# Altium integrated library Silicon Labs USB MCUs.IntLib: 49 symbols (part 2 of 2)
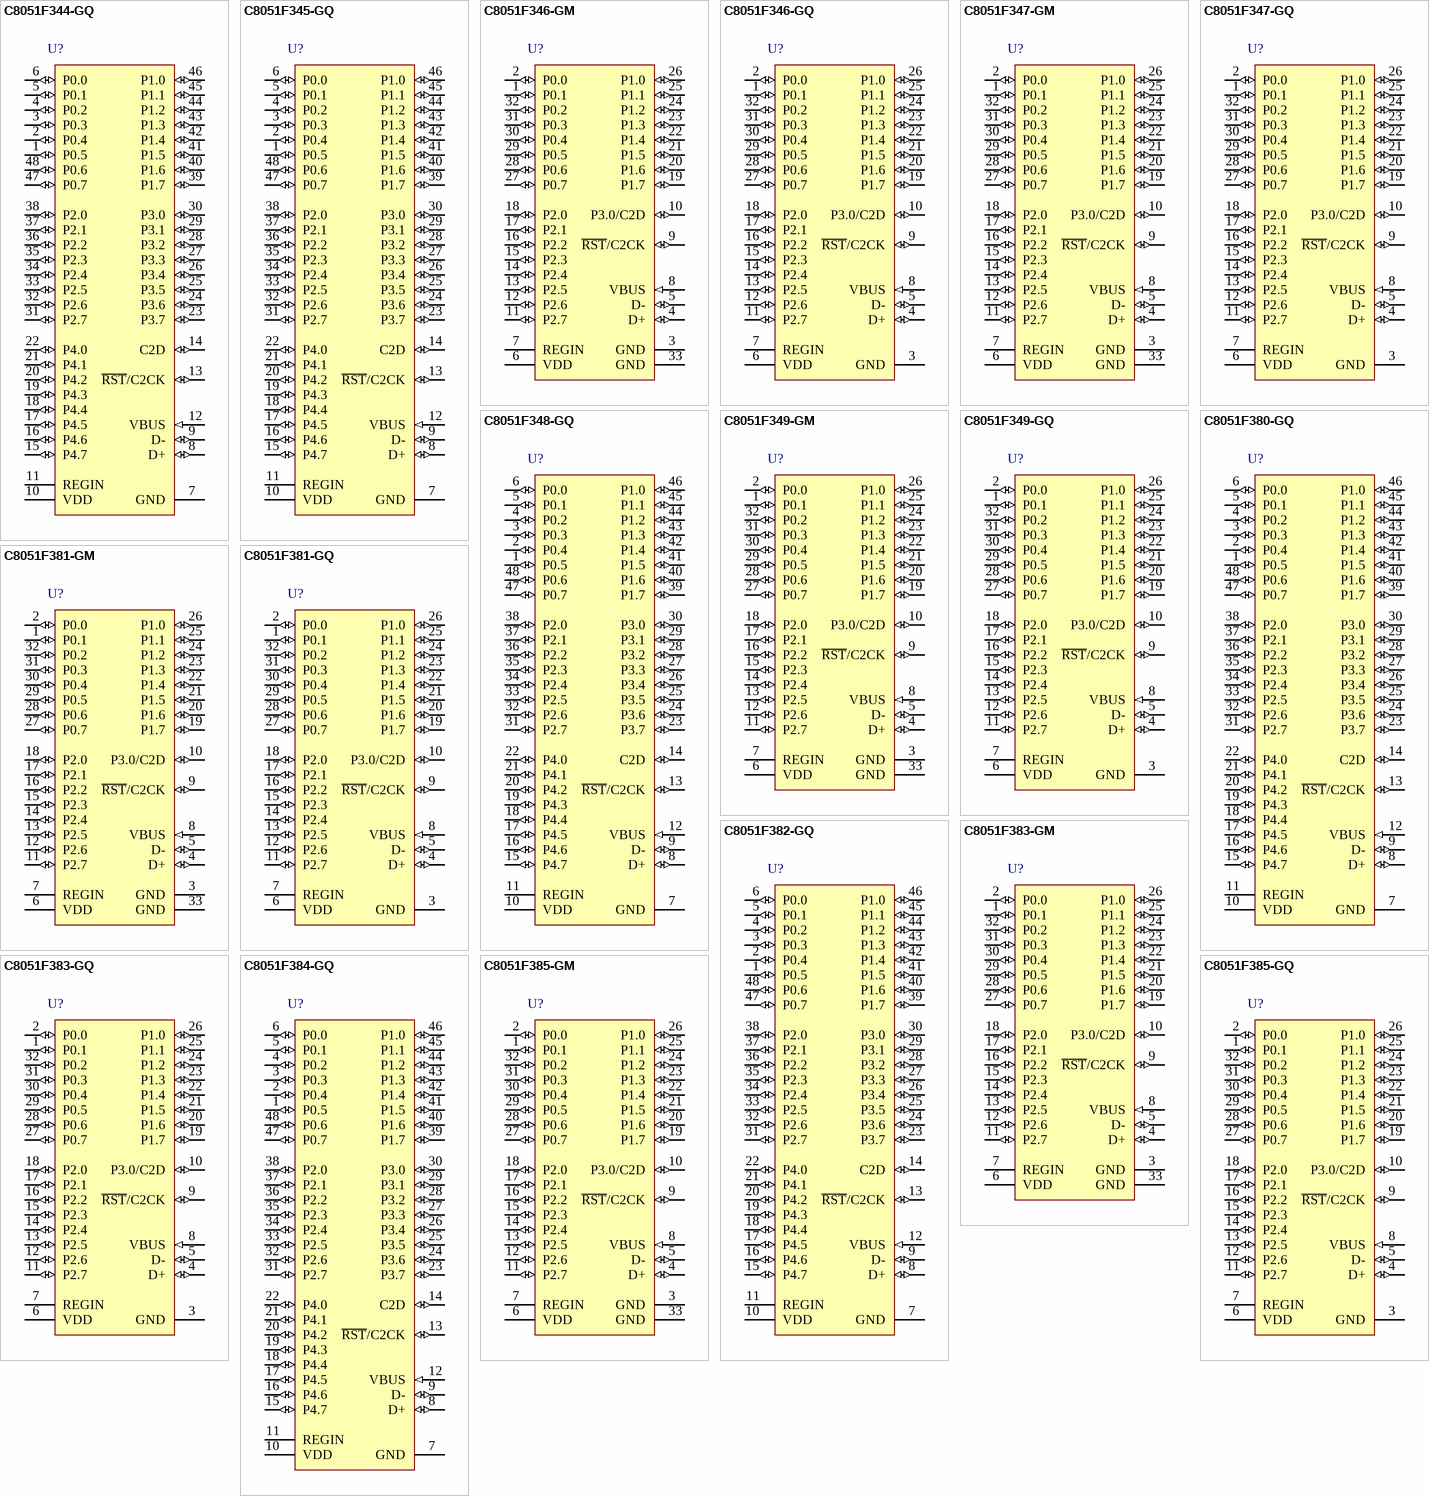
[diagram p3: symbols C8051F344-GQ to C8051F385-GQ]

## C8051F349-GQ
designator U?
Full Speed USB Flash MCU Family, 25 MHz, 2.25 kB RAM, 32 kB Flash, -40 to 85 degC, 32-pin QFP; Manufacturer: Silicon Labs; PartNumber: C8051F349-GQ; AEC-Q100: FALSE; Comparators: 2; Debug Interface: C2; Dig I/O Pins: 25; Flash: 32 kB; Internal Osc. Accuracy: +/-0.25%; MCU Core: 8051; PCA Channels: 5; RAM: 2.25 kB; Timers (16-bit): 4; Sub-Family: USB MCUs
footprint SLAB-LQFP-32_N (QFP, 32-Leads, Body 7x7mm, Pitch 0.8mm, IPC Medium Density)
footprint SLAB-LQFP-32_L (QFP, 32-Leads, Body 7x7mm, Pitch 0.8mm, IPC High Density)
footprint SLAB-LQFP-32_M (QFP, 32-Leads, Body 7x7mm, Pitch 0.8mm, IPC Low Density)
pins: 1 P0.1 (io) "Port 0.1", 2 P0.0 (io) "Port 0.0. See Section 15 for a complete description of Port 0", 3 GND (power) "Ground.", 4 D+ (io) "USB D+.", 5 D- (io) "USB D-.", 6 VDD (power) "2.7-3.6 V Power Supply Voltage Input. 3.3 V Voltage Regulator Output. See Section 8.", 7 REGIN (power) "5 V Regulator Input. This pin is the input to the on-chip voltage regulator.", 8 VBUS (in) "VBUS Sense Input. This pin should be connected to the VBUS signal of a USB network. A 5 V signal on this pin indicates a USB network connection.", 9 ~{RST}/C2CK (io), 10 P3.0/C2D (io), 11 P2.7 (io) "Port 2.7.", 12 P2.6 (io) "Port 2.6.", 13 P2.5 (io) "Port 2.5.", 14 P2.4 (io) "Port 2.4.", 15 P2.3 (io) "Port 2.3.", 16 P2.2 (io) "Port 2.2.", 17 P2.1 (io) "Port 2.1.", 18 P2.0 (io) "Port 2.0. See Section 15 for a complete description of Port 2.", 19 P1.7 (io) "Port 1.7.", 20 P1.6 (io) "Port 1.6.", 21 P1.5 (io) "Port 1.5.", 22 P1.4 (io) "Port 1.4.", 23 P1.3 (io) "Port 1.3.", 24 P1.2 (io) "Port 1.2.", 25 P1.1 (io) "Port 1.1.", 26 P1.0 (io) "Port 1.0. See Section 15 for a complete description of Port 3.", 27 P0.7 (io) "Port 0.7", 28 P0.6 (io) "Port 0.6", 29 P0.5 (io) "Port 0.5", 30 P0.4 (io) "Port 0.4", 31 P0.3 (io) "Port 0.3", 32 P0.2 (io) "Port 0.2"

## C8051F380-GQ
designator U?
Full Speed USB Flash MCU Family, 48 MHz, 4.25 kB RAM, 64 kB Flash, -40 to 85 degC, 48-pin QFP; Manufacturer: Silicon Labs; PartNumber: C8051F380-GQ; ADC 1: 10-bit, 32-ch., 500 ksps; AEC-Q100: FALSE; Comparators: 2; Debug Interface: C2; Dig I/O Pins: 40; Flash: 64 kB; Internal Osc. Accuracy: +/-0.25%; MCU Core: 8051; MHz: 48; PCA Channels: 5; RAM: 4.25 KB; Temp Sensor: TRUE; Timers (16-bit): 6; Sub-Family: USB MCUs
footprint SLAB-TQFP-48_N (QFP, 48-Leads, Body 7x7mm, Pitch 0.5mm, IPC Medium Density)
footprint SLAB-TQFP-48_L (QFP, 48-Leads, Body 7x7mm, Pitch 0.5mm, IPC High Density)
footprint SLAB-TQFP-48_M (QFP, 48-Leads, Body 7x7mm, Pitch 0.5mm, IPC Low Density)
pins: 1 P0.5 (io) "Port 0.5.", 2 P0.4 (io) "Port 0.4.", 3 P0.3 (io) "Port 0.3.", 4 P0.2 (io) "Port 0.2.", 5 P0.1 (io) "Port 0.1", 6 P0.0 (io) "Port 0.0.", 7 GND (power) "Ground.", 8 D+ (io) "USB D+.", 9 D- (io) "USB D-.", 10 VDD (power) "2.7-3.6 V Power Supply Voltage Input. 3.3 V Voltage Regulator Output.", 11 REGIN (power) "5 V Regulator Input. This pin is the input to the on-chip voltage regulator.", 12 VBUS (in) "VBUS Sense Input. This pin should be connected to the VBUS signal of a USB network. A 5 V signal on this pin indicates a USB network connection.", 13 ~{RST}/C2CK (io), 14 C2D (io) "Bi-directional data signal for the C2 Debug Interface.", 15 P4.7 (io) "Port 4.7.", 16 P4.6 (io) "Port 4.6.", 17 P4.5 (io) "Port 4.5.", 18 P4.4 (io) "Port 4.4.", 19 P4.3 (io) "Port 4.3.", 20 P4.2 (io) "Port 4.2.", 21 P4.1 (io) "Port 4.1.", 22 P4.0 (io) "Port 4.0.", 23 P3.7 (io) "Port 3.7.", 24 P3.6 (io) "Port 3.6.", 25 P3.5 (io) "Port 3.5.", 26 P3.4 (io) "Port 3.4.", 27 P3.3 (io) "Port 3.3.", 28 P3.2 (io) "Port 3.2.", 29 P3.1 (io) "Port 3.1.", 30 P3.0 (io) "Port 3.0.", 31 P2.7 (io) "Port 2.7.", 32 P2.6 (io) "Port 2.6.", 33 P2.5 (io) "Port 2.5.", 34 P2.4 (io) "Port 2.4.", 35 P2.3 (io) "Port 2.3.", 36 P2.2 (io) "Port 2.2.", 37 P2.1 (io) "Port 2.1.", 38 P2.0 (io) "Port 2.0.", 39 P1.7 (io) "Port 1.7.", 40 P1.6 (io) "Port 1.6.", 41 P1.5 (io) "Port 1.5.", 42 P1.4 (io) "Port 1.4.", 43 P1.3 (io) "Port 1.3.", 44 P1.2 (io) "Port 1.2.", 45 P1.1 (io) "Port 1.1.", 46 P1.0 (io) "Port 1.0.", 47 P0.7 (io) "Port 0.7.", 48 P0.6 (io) "Port 0.6."

## C8051F381-GM
designator U?
Full Speed USB Flash MCU Family, 48 MHz, 4.25 kB RAM, 64 kB Flash, -40 to 85 degC, 32-pin QFN; Manufacturer: Silicon Labs; PartNumber: C8051F381-GM; ADC 1: 10-bit, 21-ch., 500 ksps; AEC-Q100: FALSE; Comparators: 2; Debug Interface: C2; Dig I/O Pins: 25; Flash: 64 kB; Internal Osc. Accuracy: +/-0.25%; MCU Core: 8051; MHz: 48; PCA Channels: 5; RAM: 4.25 KB; Temp Sensor: TRUE; Timers (16-bit): 6; Sub-Family: USB MCUs
footprint SLAB-QFN-32-3300x3300TP_A_N (QFN, 32-Leads, Body 5x5mm, Pitch 0.5mm, Thermal Pad 3.3x3.3mm, IPC Medium Density)
footprint SLAB-QFN-32-3300x3300TP_A_L (QFN, 32-Leads, Body 5x5mm, Pitch 0.5mm, Thermal Pad 3.3x3.3mm, IPC High Density)
footprint SLAB-QFN-32-3300x3300TP_A_M (QFN, 32-Leads, Body 5x5mm, Pitch 0.5mm, Thermal Pad 3.3x3.3mm, IPC Low Density)
pins: 1 P0.1 (io) "Port 0.1.", 2 P0.0 (io) "Port 0.0.", 3 GND (power) "Ground.", 4 D+ (io) "USB D+.", 5 D- (io) "USB D-", 6 VDD (power) "2.7-3.6 V Power Supply Voltage Input. 3.3 V Voltage Regulator Output.", 7 REGIN (power) "5 V Regulator Input. This pin is the input to the on-chip  voltage regulator.", 8 VBUS (in) "VBUS Sense Input. This pin should be connected to the VBUS signal of a USB network. A 5 V signal on this pin indicates a USB network connection.", 9 ~{RST}/C2CK (io), 10 P3.0/C2D (io), 11 P2.7 (io) "Port 2.7.", 12 P2.6 (io) "Port 2.6.", 13 P2.5 (io) "Port 2.5.", 14 P2.4 (io) "Port 2.4.", 15 P2.3 (io) "Port 2.3.", 16 P2.2 (io) "Port 2.2.", 17 P2.1 (io) "Port 2.1.", 18 P2.0 (io) "Port 2.0.", 19 P1.7 (io) "Port 1.7.", 20 P1.6 (io) "Port 1.6.", 21 P1.5 (io) "Port 1.5.", 22 P1.4 (io) "Port 1.4.", 23 P1.3 (io) "Port 1.3.", 24 P1.2 (io) "Port 1.2.", 25 P1.1 (io) "Port 1.1.", 26 P1.0 (io) "Port 1.0.", 27 P0.7 (io) "Port 0.7.", 28 P0.6 (io) "Port 0.6.", 29 P0.5 (io) "Port 0.5.", 30 P0.4 (io) "Port 0.4.", 31 P0.3 (io) "Port 0.3.", 32 P0.2 (io) "Port 0.2.", 33 GND (power)

## C8051F381-GQ
designator U?
Full Speed USB Flash MCU Family, 48 MHz, 4.25 kB RAM, 64 kB Flash, -40 to 85 degC, 32-pin QFN; Manufacturer: Silicon Labs; PartNumber: C8051F381-GQ; ADC 1: 10-bit, 21-ch., 500 ksps; AEC-Q100: FALSE; Comparators: 2; Debug Interface: C2; Dig I/O Pins: 25; Flash: 64 kB; Internal Osc. Accuracy: +/-0.25%; MCU Core: 8051; MHz: 48; PCA Channels: 5; RAM: 4.25 KB; Temp Sensor: TRUE; Timers (16-bit): 6; Sub-Family: USB MCUs
footprint SLAB-LQFP-32_N (QFP, 32-Leads, Body 7x7mm, Pitch 0.8mm, IPC Medium Density)
footprint SLAB-LQFP-32_L (QFP, 32-Leads, Body 7x7mm, Pitch 0.8mm, IPC High Density)
footprint SLAB-LQFP-32_M (QFP, 32-Leads, Body 7x7mm, Pitch 0.8mm, IPC Low Density)
pins: 1 P0.1 (io) "Port 0.1.", 2 P0.0 (io) "Port 0.0. See Section 20 for a complete description of Port 0.", 3 GND (power) "Ground.", 4 D+ (io) "USB D+.", 5 D- (io) "USB D-", 6 VDD (power) "2.7-3.6 V Core Supply Voltage Input. 3.3 V Voltage Regulator Output. See Section 5.", 7 REGIN (power) "5 V Regulator Input. This pin is the input to the on-chip  voltage regulator.", 8 VBUS (in) "VBUS Sense Input. This pin should be connected to the VBUS signal of a USB network. A 5 V signal on this pin indicates a USB network connection.", 9 ~{RST}/C2CK (io), 10 P3.0/C2D (io), 11 P2.7 (io) "Port 2.7.", 12 P2.6 (io) "Port 2.6.", 13 P2.5 (io) "Port 2.5.", 14 P2.4 (io) "Port 2.4.", 15 P2.3 (io) "Port 2.3.", 16 P2.2 (io) "Port 2.2.", 17 P2.1 (io) "Port 2.1.", 18 P2.0 (io) "Port 2.0. See Section 20 for a complete description of Port 2.", 19 P1.7 (io) "Port 1.7.", 20 P1.6 (io) "Port 1.6.", 21 P1.5 (io) "Port 1.5.", 22 P1.4 (io) "Port 1.4.", 23 P1.3 (io) "Port 1.3.", 24 P1.2 (io) "Port 1.2.", 25 P1.1 (io) "Port 1.1.", 26 P1.0 (io) "Port 1.0. See Section 20 for a complete description of Port 1.", 27 P0.7 (io) "Port 0.7.", 28 P0.6 (io) "Port 0.6.", 29 P0.5 (io) "Port 0.5.", 30 P0.4 (io) "Port 0.4.", 31 P0.3 (io) "Port 0.3.", 32 P0.2 (io) "Port 0.2."

## C8051F382-GQ
designator U?
Full Speed USB Flash MCU Family, 48 MHz, 2.25 kB RAM, 32 kB Flash, -40 to 85 degC, 48-pin QFP; Manufacturer: Silicon Labs; PartNumber: C8051F382-GQ; ADC 1: 10-bit, 32-ch., 500 ksps; AEC-Q100: FALSE; Comparators: 2; Debug Interface: C2; Dig I/O Pins: 40; Flash: 32 kB; Internal Osc. Accuracy: +/-0.25%; MCU Core: 8051; MHz: 48; PCA Channels: 5; RAM: 2.25 KB; Temp Sensor: TRUE; Timers (16-bit): 6; Sub-Family: USB MCUs
footprint SLAB-TQFP-48_N (QFP, 48-Leads, Body 7x7mm, Pitch 0.5mm, IPC Medium Density)
footprint SLAB-TQFP-48_L (QFP, 48-Leads, Body 7x7mm, Pitch 0.5mm, IPC High Density)
footprint SLAB-TQFP-48_M (QFP, 48-Leads, Body 7x7mm, Pitch 0.5mm, IPC Low Density)
pins: 1 P0.5 (io) "Port 0.5.", 2 P0.4 (io) "Port 0.4.", 3 P0.3 (io) "Port 0.3.", 4 P0.2 (io) "Port 0.2.", 5 P0.1 (io) "Port 0.1", 6 P0.0 (io) "Port 0.0.", 7 GND (power) "Ground.", 8 D+ (io) "USB D+.", 9 D- (io) "USB D-.", 10 VDD (power) "2.7-3.6 V Power Supply Voltage Input. 3.3 V Voltage Regulator Output.", 11 REGIN (power) "5 V Regulator Input. This pin is the input to the on-chip voltage regulator.", 12 VBUS (in) "VBUS Sense Input. This pin should be connected to the VBUS signal of a USB network. A 5 V signal on this pin indicates a USB network connection.", 13 ~{RST}/C2CK (io), 14 C2D (io) "Bi-directional data signal for the C2 Debug Interface.", 15 P4.7 (io) "Port 4.7.", 16 P4.6 (io) "Port 4.6.", 17 P4.5 (io) "Port 4.5.", 18 P4.4 (io) "Port 4.4.", 19 P4.3 (io) "Port 4.3.", 20 P4.2 (io) "Port 4.2.", 21 P4.1 (io) "Port 4.1.", 22 P4.0 (io) "Port 4.0.", 23 P3.7 (io) "Port 3.7.", 24 P3.6 (io) "Port 3.6.", 25 P3.5 (io) "Port 3.5.", 26 P3.4 (io) "Port 3.4.", 27 P3.3 (io) "Port 3.3.", 28 P3.2 (io) "Port 3.2.", 29 P3.1 (io) "Port 3.1.", 30 P3.0 (io) "Port 3.0.", 31 P2.7 (io) "Port 2.7.", 32 P2.6 (io) "Port 2.6.", 33 P2.5 (io) "Port 2.5.", 34 P2.4 (io) "Port 2.4.", 35 P2.3 (io) "Port 2.3.", 36 P2.2 (io) "Port 2.2.", 37 P2.1 (io) "Port 2.1.", 38 P2.0 (io) "Port 2.0.", 39 P1.7 (io) "Port 1.7.", 40 P1.6 (io) "Port 1.6.", 41 P1.5 (io) "Port 1.5.", 42 P1.4 (io) "Port 1.4.", 43 P1.3 (io) "Port 1.3.", 44 P1.2 (io) "Port 1.2.", 45 P1.1 (io) "Port 1.1.", 46 P1.0 (io) "Port 1.0.", 47 P0.7 (io) "Port 0.7.", 48 P0.6 (io) "Port 0.6."

## C8051F383-GM
designator U?
Full Speed USB Flash MCU Family, 48 MHz, 2.25 kB RAM, 32 kB Flash, -40 to 85 degC, 32-pin QFN; Manufacturer: Silicon Labs; PartNumber: C8051F383-GM; ADC 1: 10-bit, 32-ch., 500 ksps; AEC-Q100: FALSE; Comparators: 2; Debug Interface: C2; Dig I/O Pins: 25; Flash: 32 kB; Internal Osc. Accuracy: +/-0.25%; MCU Core: 8051; MHz: 48; PCA Channels: 5; RAM: 2.25 KB; Temp Sensor: TRUE; Timers (16-bit): 6; Sub-Family: USB MCUs
footprint SLAB-QFN-32-3300x3300TP_A_N (QFN, 32-Leads, Body 5x5mm, Pitch 0.5mm, Thermal Pad 3.3x3.3mm, IPC Medium Density)
footprint SLAB-QFN-32-3300x3300TP_A_L (QFN, 32-Leads, Body 5x5mm, Pitch 0.5mm, Thermal Pad 3.3x3.3mm, IPC High Density)
footprint SLAB-QFN-32-3300x3300TP_A_M (QFN, 32-Leads, Body 5x5mm, Pitch 0.5mm, Thermal Pad 3.3x3.3mm, IPC Low Density)
pins: 1 P0.1 (io) "Port 0.1.", 2 P0.0 (io) "Port 0.0.", 3 GND (power) "Ground.", 4 D+ (io) "USB D+.", 5 D- (io) "USB D-", 6 VDD (power) "2.7-3.6 V Power Supply Voltage Input. 3.3 V Voltage Regulator Output.", 7 REGIN (power) "5 V Regulator Input. This pin is the input to the on-chip  voltage regulator.", 8 VBUS (in) "VBUS Sense Input. This pin should be connected to the VBUS signal of a USB network. A 5 V signal on this pin indicates a USB network connection.", 9 ~{RST}/C2CK (io), 10 P3.0/C2D (io), 11 P2.7 (io) "Port 2.7.", 12 P2.6 (io) "Port 2.6.", 13 P2.5 (io) "Port 2.5.", 14 P2.4 (io) "Port 2.4.", 15 P2.3 (io) "Port 2.3.", 16 P2.2 (io) "Port 2.2.", 17 P2.1 (io) "Port 2.1.", 18 P2.0 (io) "Port 2.0.", 19 P1.7 (io) "Port 1.7.", 20 P1.6 (io) "Port 1.6.", 21 P1.5 (io) "Port 1.5.", 22 P1.4 (io) "Port 1.4.", 23 P1.3 (io) "Port 1.3.", 24 P1.2 (io) "Port 1.2.", 25 P1.1 (io) "Port 1.1.", 26 P1.0 (io) "Port 1.0.", 27 P0.7 (io) "Port 0.7.", 28 P0.6 (io) "Port 0.6.", 29 P0.5 (io) "Port 0.5.", 30 P0.4 (io) "Port 0.4.", 31 P0.3 (io) "Port 0.3.", 32 P0.2 (io) "Port 0.2.", 33 GND (power)

## C8051F383-GQ
designator U?
Full Speed USB Flash MCU Family, 48 MHz, 2.25 kB RAM, 32 kB Flash, -40 to 85 degC, 32-pin QFN; Manufacturer: Silicon Labs; PartNumber: C8051F383-GQ; ADC 1: 10-bit, 32-ch., 500 ksps; AEC-Q100: FALSE; Comparators: 2; Debug Interface: C2; Dig I/O Pins: 25; Flash: 32 kB; Internal Osc. Accuracy: +/-0.25%; MCU Core: 8051; MHz: 48; PCA Channels: 5; RAM: 2.25 KB; Temp Sensor: TRUE; Timers (16-bit): 6; Sub-Family: USB MCUs
footprint SLAB-LQFP-32_N (QFP, 32-Leads, Body 7x7mm, Pitch 0.8mm, IPC Medium Density)
footprint SLAB-LQFP-32_L (QFP, 32-Leads, Body 7x7mm, Pitch 0.8mm, IPC High Density)
footprint SLAB-LQFP-32_M (QFP, 32-Leads, Body 7x7mm, Pitch 0.8mm, IPC Low Density)
pins: 1 P0.1 (io) "Port 0.1.", 2 P0.0 (io) "Port 0.0. See Section 20 for a complete description of Port 0.", 3 GND (power) "Ground.", 4 D+ (io) "USB D+.", 5 D- (io) "USB D-", 6 VDD (power) "2.7-3.6 V Core Supply Voltage Input. 3.3 V Voltage Regulator Output. See Section 5.", 7 REGIN (power) "5 V Regulator Input. This pin is the input to the on-chip  voltage regulator.", 8 VBUS (in) "VBUS Sense Input. This pin should be connected to the VBUS signal of a USB network. A 5 V signal on this pin indicates a USB network connection.", 9 ~{RST}/C2CK (io), 10 P3.0/C2D (io), 11 P2.7 (io) "Port 2.7.", 12 P2.6 (io) "Port 2.6.", 13 P2.5 (io) "Port 2.5.", 14 P2.4 (io) "Port 2.4.", 15 P2.3 (io) "Port 2.3.", 16 P2.2 (io) "Port 2.2.", 17 P2.1 (io) "Port 2.1.", 18 P2.0 (io) "Port 2.0. See Section 20 for a complete description of Port 2.", 19 P1.7 (io) "Port 1.7.", 20 P1.6 (io) "Port 1.6.", 21 P1.5 (io) "Port 1.5.", 22 P1.4 (io) "Port 1.4.", 23 P1.3 (io) "Port 1.3.", 24 P1.2 (io) "Port 1.2.", 25 P1.1 (io) "Port 1.1.", 26 P1.0 (io) "Port 1.0. See Section 20 for a complete description of Port 1.", 27 P0.7 (io) "Port 0.7.", 28 P0.6 (io) "Port 0.6.", 29 P0.5 (io) "Port 0.5.", 30 P0.4 (io) "Port 0.4.", 31 P0.3 (io) "Port 0.3.", 32 P0.2 (io) "Port 0.2."

## C8051F384-GQ
designator U?
Full Speed USB Flash MCU Family, 48 MHz, 4.25 kB RAM, 64 kB Flash, -40 to 85 degC, 48-pin QFP; Manufacturer: Silicon Labs; PartNumber: C8051F384-GQ; AEC-Q100: FALSE; Comparators: 2; Debug Interface: C2; Dig I/O Pins: 40; Flash: 64 kB; Internal Osc. Accuracy: +/-0.25%; MCU Core: 8051; MHz: 48; PCA Channels: 5; RAM: 4.25 KB; Timers (16-bit): 6; Sub-Family: USB MCUs
footprint SLAB-TQFP-48_N (QFP, 48-Leads, Body 7x7mm, Pitch 0.5mm, IPC Medium Density)
footprint SLAB-TQFP-48_L (QFP, 48-Leads, Body 7x7mm, Pitch 0.5mm, IPC High Density)
footprint SLAB-TQFP-48_M (QFP, 48-Leads, Body 7x7mm, Pitch 0.5mm, IPC Low Density)
pins: 1 P0.5 (io) "Port 0.5.", 2 P0.4 (io) "Port 0.4.", 3 P0.3 (io) "Port 0.3.", 4 P0.2 (io) "Port 0.2.", 5 P0.1 (io) "Port 0.1", 6 P0.0 (io) "Port 0.0.", 7 GND (power) "Ground.", 8 D+ (io) "USB D+.", 9 D- (io) "USB D-.", 10 VDD (power) "2.7-3.6 V Power Supply Voltage Input. 3.3 V Voltage Regulator Output.", 11 REGIN (power) "5 V Regulator Input. This pin is the input to the on-chip voltage regulator.", 12 VBUS (in) "VBUS Sense Input. This pin should be connected to the VBUS signal of a USB network. A 5 V signal on this pin indicates a USB network connection.", 13 ~{RST}/C2CK (io), 14 C2D (io) "Bi-directional data signal for the C2 Debug Interface.", 15 P4.7 (io) "Port 4.7.", 16 P4.6 (io) "Port 4.6.", 17 P4.5 (io) "Port 4.5.", 18 P4.4 (io) "Port 4.4.", 19 P4.3 (io) "Port 4.3.", 20 P4.2 (io) "Port 4.2.", 21 P4.1 (io) "Port 4.1.", 22 P4.0 (io) "Port 4.0.", 23 P3.7 (io) "Port 3.7.", 24 P3.6 (io) "Port 3.6.", 25 P3.5 (io) "Port 3.5.", 26 P3.4 (io) "Port 3.4.", 27 P3.3 (io) "Port 3.3.", 28 P3.2 (io) "Port 3.2.", 29 P3.1 (io) "Port 3.1.", 30 P3.0 (io) "Port 3.0.", 31 P2.7 (io) "Port 2.7.", 32 P2.6 (io) "Port 2.6.", 33 P2.5 (io) "Port 2.5.", 34 P2.4 (io) "Port 2.4.", 35 P2.3 (io) "Port 2.3.", 36 P2.2 (io) "Port 2.2.", 37 P2.1 (io) "Port 2.1.", 38 P2.0 (io) "Port 2.0.", 39 P1.7 (io) "Port 1.7.", 40 P1.6 (io) "Port 1.6.", 41 P1.5 (io) "Port 1.5.", 42 P1.4 (io) "Port 1.4.", 43 P1.3 (io) "Port 1.3.", 44 P1.2 (io) "Port 1.2.", 45 P1.1 (io) "Port 1.1.", 46 P1.0 (io) "Port 1.0.", 47 P0.7 (io) "Port 0.7.", 48 P0.6 (io) "Port 0.6."

## C8051F385-GM
designator U?
Full Speed USB Flash MCU Family, 48 MHz, 4.25 kB RAM, 64 kB Flash, -40 to 85 degC, 32-pin QFN; Manufacturer: Silicon Labs; PartNumber: C8051F385-GM; AEC-Q100: FALSE; Comparators: 2; Debug Interface: C2; Dig I/O Pins: 25; Flash: 64 kB; Internal Osc. Accuracy: +/-0.25%; MCU Core: 8051; MHz: 48; PCA Channels: 5; RAM: 4.25 KB; Timers (16-bit): 6; Sub-Family: USB MCUs
footprint SLAB-QFN-32-3300x3300TP_A_N (QFN, 32-Leads, Body 5x5mm, Pitch 0.5mm, Thermal Pad 3.3x3.3mm, IPC Medium Density)
footprint SLAB-QFN-32-3300x3300TP_A_L (QFN, 32-Leads, Body 5x5mm, Pitch 0.5mm, Thermal Pad 3.3x3.3mm, IPC High Density)
footprint SLAB-QFN-32-3300x3300TP_A_M (QFN, 32-Leads, Body 5x5mm, Pitch 0.5mm, Thermal Pad 3.3x3.3mm, IPC Low Density)
pins: 1 P0.1 (io) "Port 0.1.", 2 P0.0 (io) "Port 0.0.", 3 GND (power) "Ground.", 4 D+ (io) "USB D+.", 5 D- (io) "USB D-", 6 VDD (power) "2.7-3.6 V Power Supply Voltage Input. 3.3 V Voltage Regulator Output.", 7 REGIN (power) "5 V Regulator Input. This pin is the input to the on-chip  voltage regulator.", 8 VBUS (in) "VBUS Sense Input. This pin should be connected to the VBUS signal of a USB network. A 5 V signal on this pin indicates a USB network connection.", 9 ~{RST}/C2CK (io), 10 P3.0/C2D (io), 11 P2.7 (io) "Port 2.7.", 12 P2.6 (io) "Port 2.6.", 13 P2.5 (io) "Port 2.5.", 14 P2.4 (io) "Port 2.4.", 15 P2.3 (io) "Port 2.3.", 16 P2.2 (io) "Port 2.2.", 17 P2.1 (io) "Port 2.1.", 18 P2.0 (io) "Port 2.0.", 19 P1.7 (io) "Port 1.7.", 20 P1.6 (io) "Port 1.6.", 21 P1.5 (io) "Port 1.5.", 22 P1.4 (io) "Port 1.4.", 23 P1.3 (io) "Port 1.3.", 24 P1.2 (io) "Port 1.2.", 25 P1.1 (io) "Port 1.1.", 26 P1.0 (io) "Port 1.0.", 27 P0.7 (io) "Port 0.7.", 28 P0.6 (io) "Port 0.6.", 29 P0.5 (io) "Port 0.5.", 30 P0.4 (io) "Port 0.4.", 31 P0.3 (io) "Port 0.3.", 32 P0.2 (io) "Port 0.2.", 33 GND (power)

## C8051F385-GQ
designator U?
Full Speed USB Flash MCU Family, 48 MHz, 4.25 kB RAM, 64 kB Flash, -40 to 85 degC, 32-pin QFN; Manufacturer: Silicon Labs; PartNumber: C8051F385-GQ; AEC-Q100: FALSE; Comparators: 2; Debug Interface: C2; Dig I/O Pins: 25; Flash: 64 kB; Internal Osc. Accuracy: +/-0.25%; MCU Core: 8051; MHz: 48; PCA Channels: 5; RAM: 4.25 KB; Timers (16-bit): 6; Sub-Family: USB MCUs
footprint SLAB-LQFP-32_N (QFP, 32-Leads, Body 7x7mm, Pitch 0.8mm, IPC Medium Density)
footprint SLAB-LQFP-32_L (QFP, 32-Leads, Body 7x7mm, Pitch 0.8mm, IPC High Density)
footprint SLAB-LQFP-32_M (QFP, 32-Leads, Body 7x7mm, Pitch 0.8mm, IPC Low Density)
pins: 1 P0.1 (io) "Port 0.1.", 2 P0.0 (io) "Port 0.0. See Section 20 for a complete description of Port 0.", 3 GND (power) "Ground.", 4 D+ (io) "USB D+.", 5 D- (io) "USB D-", 6 VDD (power) "2.7-3.6 V Core Supply Voltage Input. 3.3 V Voltage Regulator Output. See Section 5.", 7 REGIN (power) "5 V Regulator Input. This pin is the input to the on-chip  voltage regulator.", 8 VBUS (in) "VBUS Sense Input. This pin should be connected to the VBUS signal of a USB network. A 5 V signal on this pin indicates a USB network connection.", 9 ~{RST}/C2CK (io), 10 P3.0/C2D (io), 11 P2.7 (io) "Port 2.7.", 12 P2.6 (io) "Port 2.6.", 13 P2.5 (io) "Port 2.5.", 14 P2.4 (io) "Port 2.4.", 15 P2.3 (io) "Port 2.3.", 16 P2.2 (io) "Port 2.2.", 17 P2.1 (io) "Port 2.1.", 18 P2.0 (io) "Port 2.0. See Section 20 for a complete description of Port 2.", 19 P1.7 (io) "Port 1.7.", 20 P1.6 (io) "Port 1.6.", 21 P1.5 (io) "Port 1.5.", 22 P1.4 (io) "Port 1.4.", 23 P1.3 (io) "Port 1.3.", 24 P1.2 (io) "Port 1.2.", 25 P1.1 (io) "Port 1.1.", 26 P1.0 (io) "Port 1.0. See Section 20 for a complete description of Port 1.", 27 P0.7 (io) "Port 0.7.", 28 P0.6 (io) "Port 0.6.", 29 P0.5 (io) "Port 0.5.", 30 P0.4 (io) "Port 0.4.", 31 P0.3 (io) "Port 0.3.", 32 P0.2 (io) "Port 0.2."

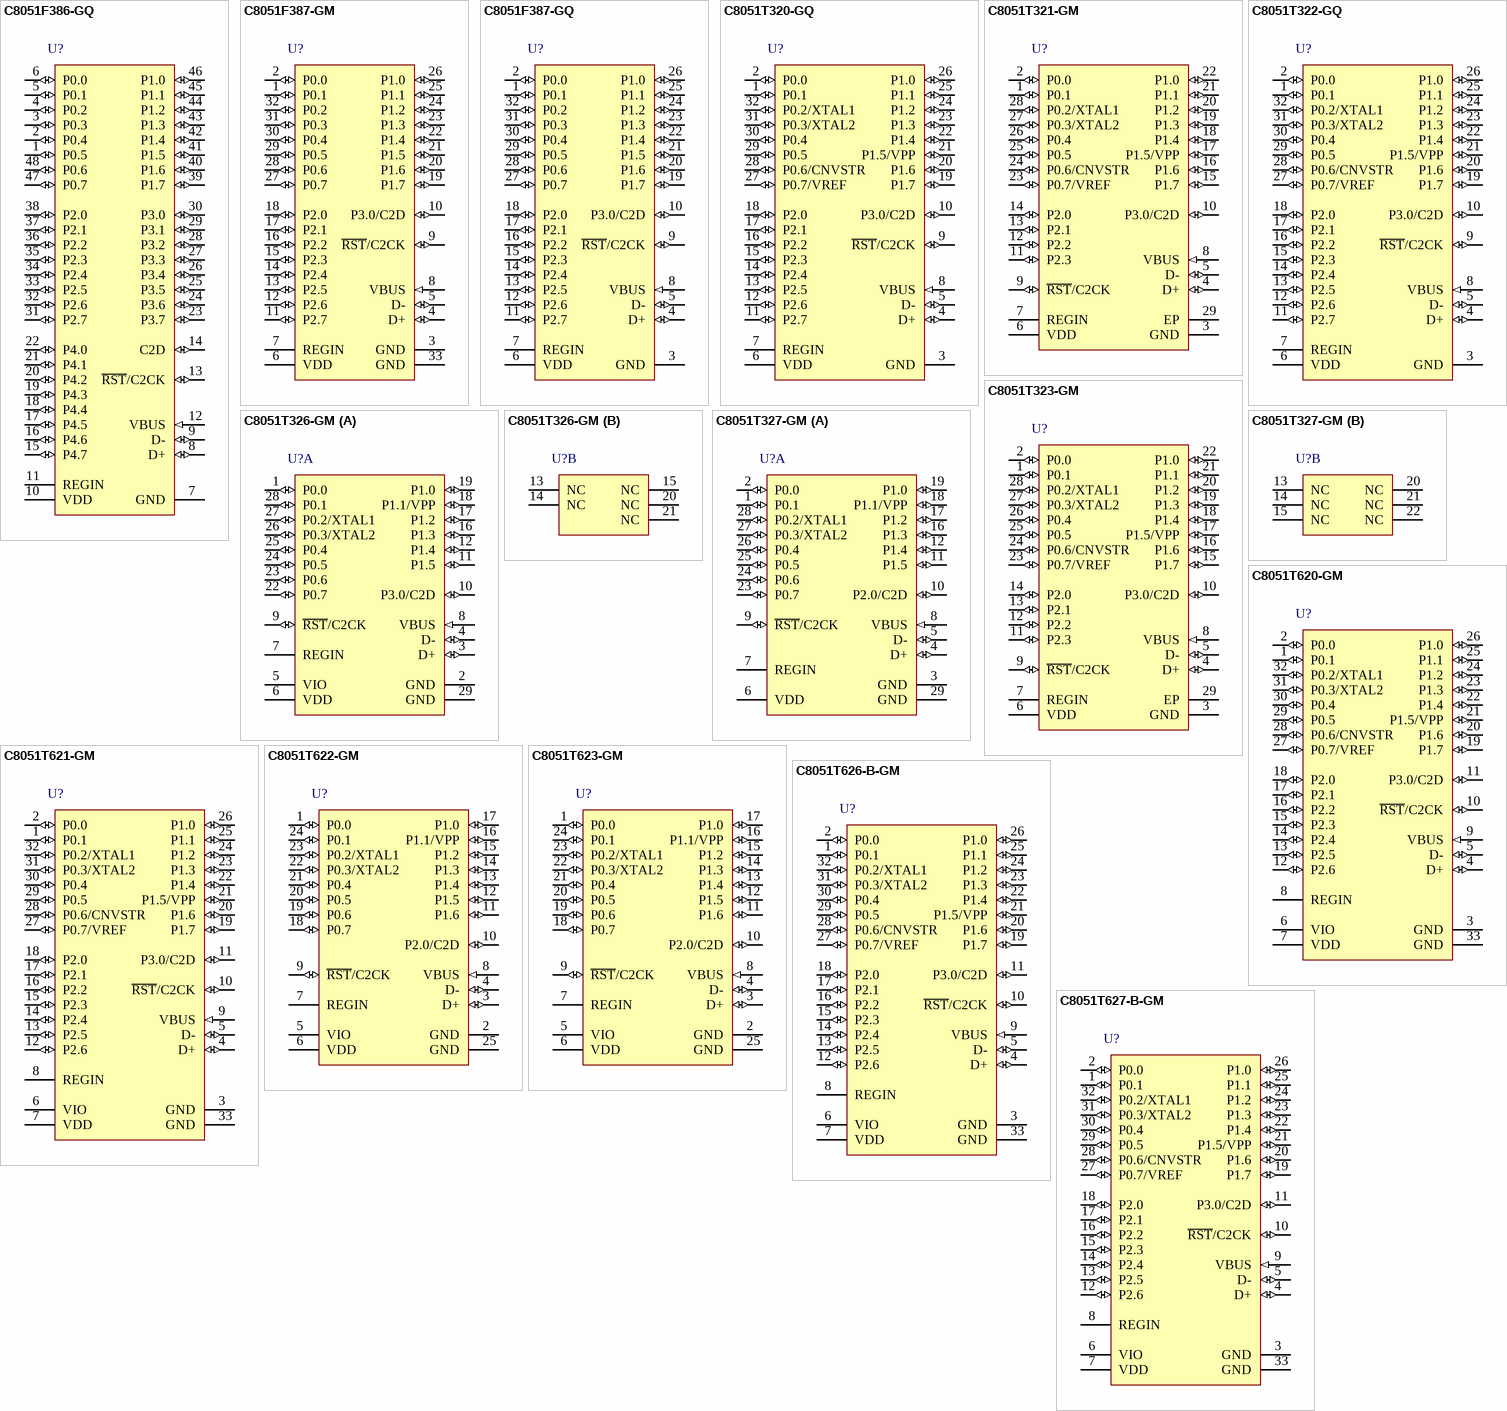
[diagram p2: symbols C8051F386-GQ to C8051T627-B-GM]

## C8051F386-GQ
designator U?
Full Speed USB Flash MCU Family, 48 MHz, 2.25 kB RAM, 32 kB Flash, -40 to 85 degC, 48-pin QFP; Manufacturer: Silicon Labs; PartNumber: C8051F386-GQ; AEC-Q100: FALSE; Comparators: 2; Debug Interface: C2; Dig I/O Pins: 40; Flash: 32 kB; Internal Osc. Accuracy: +/-0.25%; MCU Core: 8051; MHz: 48; PCA Channels: 5; RAM: 2.25 KB; Timers (16-bit): 6; Sub-Family: USB MCUs
footprint SLAB-TQFP-48_N (QFP, 48-Leads, Body 7x7mm, Pitch 0.5mm, IPC Medium Density)
footprint SLAB-TQFP-48_L (QFP, 48-Leads, Body 7x7mm, Pitch 0.5mm, IPC High Density)
footprint SLAB-TQFP-48_M (QFP, 48-Leads, Body 7x7mm, Pitch 0.5mm, IPC Low Density)
pins: 1 P0.5 (io) "Port 0.5.", 2 P0.4 (io) "Port 0.4.", 3 P0.3 (io) "Port 0.3.", 4 P0.2 (io) "Port 0.2.", 5 P0.1 (io) "Port 0.1", 6 P0.0 (io) "Port 0.0.", 7 GND (power) "Ground.", 8 D+ (io) "USB D+.", 9 D- (io) "USB D-.", 10 VDD (power) "2.7-3.6 V Power Supply Voltage Input. 3.3 V Voltage Regulator Output.", 11 REGIN (power) "5 V Regulator Input. This pin is the input to the on-chip voltage regulator.", 12 VBUS (in) "VBUS Sense Input. This pin should be connected to the VBUS signal of a USB network. A 5 V signal on this pin indicates a USB network connection.", 13 ~{RST}/C2CK (io), 14 C2D (io) "Bi-directional data signal for the C2 Debug Interface.", 15 P4.7 (io) "Port 4.7.", 16 P4.6 (io) "Port 4.6.", 17 P4.5 (io) "Port 4.5.", 18 P4.4 (io) "Port 4.4.", 19 P4.3 (io) "Port 4.3.", 20 P4.2 (io) "Port 4.2.", 21 P4.1 (io) "Port 4.1.", 22 P4.0 (io) "Port 4.0.", 23 P3.7 (io) "Port 3.7.", 24 P3.6 (io) "Port 3.6.", 25 P3.5 (io) "Port 3.5.", 26 P3.4 (io) "Port 3.4.", 27 P3.3 (io) "Port 3.3.", 28 P3.2 (io) "Port 3.2.", 29 P3.1 (io) "Port 3.1.", 30 P3.0 (io) "Port 3.0.", 31 P2.7 (io) "Port 2.7.", 32 P2.6 (io) "Port 2.6.", 33 P2.5 (io) "Port 2.5.", 34 P2.4 (io) "Port 2.4.", 35 P2.3 (io) "Port 2.3.", 36 P2.2 (io) "Port 2.2.", 37 P2.1 (io) "Port 2.1.", 38 P2.0 (io) "Port 2.0.", 39 P1.7 (io) "Port 1.7.", 40 P1.6 (io) "Port 1.6.", 41 P1.5 (io) "Port 1.5.", 42 P1.4 (io) "Port 1.4.", 43 P1.3 (io) "Port 1.3.", 44 P1.2 (io) "Port 1.2.", 45 P1.1 (io) "Port 1.1.", 46 P1.0 (io) "Port 1.0.", 47 P0.7 (io) "Port 0.7.", 48 P0.6 (io) "Port 0.6."

## C8051F387-GM
designator U?
Full Speed USB Flash MCU Family, 48 MHz, 2.25 kB RAM, 32 kB Flash, -40 to 85 degC, 32-pin QFN; Manufacturer: Silicon Labs; PartNumber: C8051F387-GM; AEC-Q100: FALSE; Comparators: 2; Debug Interface: C2; Dig I/O Pins: 25; Flash: 32 kB; Internal Osc. Accuracy: +/-0.25%; MCU Core: 8051; MHz: 48; PCA Channels: 5; RAM: 2.25 KB; Timers (16-bit): 6; Sub-Family: USB MCUs
footprint SLAB-QFN-32-3300x3300TP_A_N (QFN, 32-Leads, Body 5x5mm, Pitch 0.5mm, Thermal Pad 3.3x3.3mm, IPC Medium Density)
footprint SLAB-QFN-32-3300x3300TP_A_L (QFN, 32-Leads, Body 5x5mm, Pitch 0.5mm, Thermal Pad 3.3x3.3mm, IPC High Density)
footprint SLAB-QFN-32-3300x3300TP_A_M (QFN, 32-Leads, Body 5x5mm, Pitch 0.5mm, Thermal Pad 3.3x3.3mm, IPC Low Density)
pins: 1 P0.1 (io) "Port 0.1.", 2 P0.0 (io) "Port 0.0.", 3 GND (power) "Ground.", 4 D+ (io) "USB D+.", 5 D- (io) "USB D-", 6 VDD (power) "2.7-3.6 V Power Supply Voltage Input. 3.3 V Voltage Regulator Output.", 7 REGIN (power) "5 V Regulator Input. This pin is the input to the on-chip  voltage regulator.", 8 VBUS (in) "VBUS Sense Input. This pin should be connected to the VBUS signal of a USB network. A 5 V signal on this pin indicates a USB network connection.", 9 ~{RST}/C2CK (io), 10 P3.0/C2D (io), 11 P2.7 (io) "Port 2.7.", 12 P2.6 (io) "Port 2.6.", 13 P2.5 (io) "Port 2.5.", 14 P2.4 (io) "Port 2.4.", 15 P2.3 (io) "Port 2.3.", 16 P2.2 (io) "Port 2.2.", 17 P2.1 (io) "Port 2.1.", 18 P2.0 (io) "Port 2.0.", 19 P1.7 (io) "Port 1.7.", 20 P1.6 (io) "Port 1.6.", 21 P1.5 (io) "Port 1.5.", 22 P1.4 (io) "Port 1.4.", 23 P1.3 (io) "Port 1.3.", 24 P1.2 (io) "Port 1.2.", 25 P1.1 (io) "Port 1.1.", 26 P1.0 (io) "Port 1.0.", 27 P0.7 (io) "Port 0.7.", 28 P0.6 (io) "Port 0.6.", 29 P0.5 (io) "Port 0.5.", 30 P0.4 (io) "Port 0.4.", 31 P0.3 (io) "Port 0.3.", 32 P0.2 (io) "Port 0.2.", 33 GND (power)

## C8051F387-GQ
designator U?
Full Speed USB Flash MCU Family, 48 MHz, 2.25 kB RAM, 32 kB Flash, -40 to 85 degC, 32-pin QFN; Manufacturer: Silicon Labs; PartNumber: C8051F387-GQ; AEC-Q100: FALSE; Comparators: 2; Debug Interface: C2; Dig I/O Pins: 25; Flash: 32 kB; Internal Osc. Accuracy: +/-0.25%; MCU Core: 8051; MHz: 48; PCA Channels: 5; RAM: 2.25 KB; Timers (16-bit): 6; Sub-Family: USB MCUs
footprint SLAB-LQFP-32_N (QFP, 32-Leads, Body 7x7mm, Pitch 0.8mm, IPC Medium Density)
footprint SLAB-LQFP-32_L (QFP, 32-Leads, Body 7x7mm, Pitch 0.8mm, IPC High Density)
footprint SLAB-LQFP-32_M (QFP, 32-Leads, Body 7x7mm, Pitch 0.8mm, IPC Low Density)
pins: 1 P0.1 (io) "Port 0.1.", 2 P0.0 (io) "Port 0.0. See Section 20 for a complete description of Port 0.", 3 GND (power) "Ground.", 4 D+ (io) "USB D+.", 5 D- (io) "USB D-", 6 VDD (power) "2.7-3.6 V Core Supply Voltage Input. 3.3 V Voltage Regulator Output. See Section 5.", 7 REGIN (power) "5 V Regulator Input. This pin is the input to the on-chip  voltage regulator.", 8 VBUS (in) "VBUS Sense Input. This pin should be connected to the VBUS signal of a USB network. A 5 V signal on this pin indicates a USB network connection.", 9 ~{RST}/C2CK (io), 10 P3.0/C2D (io), 11 P2.7 (io) "Port 2.7.", 12 P2.6 (io) "Port 2.6.", 13 P2.5 (io) "Port 2.5.", 14 P2.4 (io) "Port 2.4.", 15 P2.3 (io) "Port 2.3.", 16 P2.2 (io) "Port 2.2.", 17 P2.1 (io) "Port 2.1.", 18 P2.0 (io) "Port 2.0. See Section 20 for a complete description of Port 2.", 19 P1.7 (io) "Port 1.7.", 20 P1.6 (io) "Port 1.6.", 21 P1.5 (io) "Port 1.5.", 22 P1.4 (io) "Port 1.4.", 23 P1.3 (io) "Port 1.3.", 24 P1.2 (io) "Port 1.2.", 25 P1.1 (io) "Port 1.1.", 26 P1.0 (io) "Port 1.0. See Section 20 for a complete description of Port 1.", 27 P0.7 (io) "Port 0.7.", 28 P0.6 (io) "Port 0.6.", 29 P0.5 (io) "Port 0.5.", 30 P0.4 (io) "Port 0.4.", 31 P0.3 (io) "Port 0.3.", 32 P0.2 (io) "Port 0.2."

## C8051T320-GQ
designator U?
Full Speed USB EPROM MCU Family, 48 MHz, 1.25 kB RAM, 16 kB Flash, -40 to 85 degC, 32-pin QFP; Manufacturer: Silicon Labs; PartNumber: C8051T320-GQ; ADC 1: 10-bit, 16-ch., 500 ksps; AEC-Q100: FALSE; Comparators: 2; Debug Interface: C2; Dig I/O Pins: 25; Flash: 16 kB; MCU Core: 8051; MHz: 48; PCA Channels: 5; RAM: 1.25 KB; Temp Sensor: TRUE; Timers (16-bit): 4; Sub-Family: USB MCUs
footprint SLAB-LQFP-32_N (QFP, 32-Leads, Body 7x7mm, Pitch 0.8mm, IPC Medium Density)
footprint SLAB-LQFP-32_L (QFP, 32-Leads, Body 7x7mm, Pitch 0.8mm, IPC High Density)
footprint SLAB-LQFP-32_M (QFP, 32-Leads, Body 7x7mm, Pitch 0.8mm, IPC Low Density)
pins: 1 P0.1 (io) "Port 0.1.", 2 P0.0 (io) "Port 0.0.", 3 GND (power) "Ground.", 4 D+ (io) "USB D+.", 5 D- (io) "USB D+.", 6 VDD (power) "Power Supply Voltage.", 7 REGIN (power) "5 V Regulator Input. This pin is the input to the on-chip voltage regulator", 8 VBUS (in) "VBUS Sense Input. This pin should be connected to the VBUS signal of a USB network. A 5 V signal on this pin indicates a USB network connection.", 9 ~{RST}/C2CK (io), 10 P3.0/C2D (io), 11 P2.7 (io) "Port 2.7.", 12 P2.6 (io) "Port 2.6.", 13 P2.5 (io) "Port 2.5.", 14 P2.4 (io) "Port 2.4.", 15 P2.3 (io) "Port 2.3.", 16 P2.2 (io) "Port 2.2.", 17 P2.1 (io) "Port 2.1.", 18 P2.0 (io) "Port 2.0.", 19 P1.7 (io) "Port 1.7.", 20 P1.6 (io) "Port 1.6.", 21 P1.5/VPP (io), 22 P1.4 (io) "Port 1.4.", 23 P1.3 (io) "Port 1.3.", 24 P1.2 (io) "Port 1.2.", 25 P1.1 (io) "Port 1.1.", 26 P1.0 (io) "Port 1.0.", 27 P0.7/VREF (io), 28 P0.6/CNVSTR (io), 29 P0.5 (io) "Port 0.5.", 30 P0.4 (io) "Port 0.4.", 31 P0.3/XTAL2 (io), 32 P0.2/XTAL1 (io)

## C8051T321-GM
designator U?
Full Speed USB EPROM MCU Family, 48 MHz, 1.25 kB RAM, 16 kB Flash, -40 to 85 degC, 28-pin QFN; Manufacturer: Silicon Labs; PartNumber: C8051T321-GM; ADC 1: 10-bit, 16-ch., 500 ksps; AEC-Q100: FALSE; Comparators: 2; Debug Interface: C2; Dig I/O Pins: 21; Flash: 16 kB; MCU Core: 8051; MHz: 48; PCA Channels: 5; RAM: 1.25 KB; Temp Sensor: TRUE; Timers (16-bit): 4; Sub-Family: USB MCUs
footprint SLAB-QFN-28-3125x3125TP_N (QFN, 28-Leads, Body 5x5mm, Pitch 0.5mm, Thermal Pad 3.13x3.13mm, IPC Medium Density)
footprint SLAB-QFN-28-3125x3125TP_L (QFN, 28-Leads, Body 5x5mm, Pitch 0.5mm, Thermal Pad 3.13x3.13mm, IPC High Density)
footprint SLAB-QFN-28-3125x3125TP_M (QFN, 28-Leads, Body 5x5mm, Pitch 0.5mm, Thermal Pad 3.13x3.13mm, IPC Low Density)
pins: 1 P0.1 (io) "Port 0.1.", 2 P0.0 (io) "Port 0.0.", 3 GND (power) "Ground.", 4 D+ (io) "USB D+.", 5 D- (io) "USB D-.", 6 VDD (power) "Power Supply Voltage.", 7 REGIN (power) "5 V Regulator Input. This pin is the input to the on-chip voltage regulator", 8 VBUS (in) "VBUS Sense Input. This pin should be connected to the VBUS signal of a USB network. A 5 V signal on this pin indicates a USB network connection.", 9 ~{RST}/C2CK (io), 10 P3.0/C2D (io), 11 P2.3 (io) "Port 2.3.", 12 P2.2 (io) "Port 2.2.", 13 P2.1 (io) "Port 2.1.", 14 P2.0 (io) "Port 2.0.", 15 P1.7 (io) "Port 1.7.", 16 P1.6 (io) "Port 1.6.", 17 P1.5/VPP (io), 18 P1.4 (io) "Port 1.4.", 19 P1.3 (io) "Port 1.3.", 20 P1.2 (io) "Port 1.2.", 21 P1.1 (io) "Port 1.1.", 22 P1.0 (io) "Port 1.0.", 23 P0.7/VREF (io), 24 P0.6/CNVSTR (io), 25 P0.5 (io) "Port 0.5.", 26 P0.4 (io) "Port 0.4.", 27 P0.3/XTAL2 (io), 28 P0.2/XTAL1 (io), 29 EP (power)

## C8051T322-GQ
designator U?
Full Speed USB EPROM MCU Family, 48 MHz, 1.25 kB RAM, 16 kB Flash, -40 to 85 degC, 32-pin QFP; Manufacturer: Silicon Labs; PartNumber: C8051T322-GQ; AEC-Q100: FALSE; Comparators: 2; Debug Interface: C2; Dig I/O Pins: 25; Flash: 16 kB; MCU Core: 8051; MHz: 48; PCA Channels: 5; RAM: 1.25 kB; Temp Sensor: TRUE; Timers (16-bit): 4; Sub-Family: USB MCUs
footprint SLAB-LQFP-32_N (QFP, 32-Leads, Body 7x7mm, Pitch 0.8mm, IPC Medium Density)
footprint SLAB-LQFP-32_L (QFP, 32-Leads, Body 7x7mm, Pitch 0.8mm, IPC High Density)
footprint SLAB-LQFP-32_M (QFP, 32-Leads, Body 7x7mm, Pitch 0.8mm, IPC Low Density)
pins: 1 P0.1 (io) "Port 0.1.", 2 P0.0 (io) "Port 0.0.", 3 GND (power) "Ground.", 4 D+ (io) "USB D+.", 5 D- (io) "USB D+.", 6 VDD (power) "Power Supply Voltage.", 7 REGIN (power) "5 V Regulator Input. This pin is the input to the on-chip voltage regulator", 8 VBUS (in) "VBUS Sense Input. This pin should be connected to the VBUS signal of a USB network. A 5 V signal on this pin indicates a USB network connection.", 9 ~{RST}/C2CK (io), 10 P3.0/C2D (io), 11 P2.7 (io) "Port 2.7.", 12 P2.6 (io) "Port 2.6.", 13 P2.5 (io) "Port 2.5.", 14 P2.4 (io) "Port 2.4.", 15 P2.3 (io) "Port 2.3.", 16 P2.2 (io) "Port 2.2.", 17 P2.1 (io) "Port 2.1.", 18 P2.0 (io) "Port 2.0.", 19 P1.7 (io) "Port 1.7.", 20 P1.6 (io) "Port 1.6.", 21 P1.5/VPP (io), 22 P1.4 (io) "Port 1.4.", 23 P1.3 (io) "Port 1.3.", 24 P1.2 (io) "Port 1.2.", 25 P1.1 (io) "Port 1.1.", 26 P1.0 (io) "Port 1.0.", 27 P0.7/VREF (io), 28 P0.6/CNVSTR (io), 29 P0.5 (io) "Port 0.5.", 30 P0.4 (io) "Port 0.4.", 31 P0.3/XTAL2 (io), 32 P0.2/XTAL1 (io)

## C8051T323-GM
designator U?
Full Speed USB EPROM MCU Family, 48 MHz, 1.25 kB RAM, 16 kB Flash, -40 to 85 degC, 28-pin QFN; Manufacturer: Silicon Labs; PartNumber: C8051T323-GM; AEC-Q100: FALSE; Comparators: 2; Debug Interface: C2; Dig I/O Pins: 21; Flash: 16 kB; MCU Core: 8051; MHz: 48; PCA Channels: 5; RAM: 1.25 KB; Temp Sensor: TRUE; Timers (16-bit): 4; Sub-Family: USB MCUs
footprint SLAB-QFN-28-3125x3125TP_N (QFN, 28-Leads, Body 5x5mm, Pitch 0.5mm, Thermal Pad 3.13x3.13mm, IPC Medium Density)
footprint SLAB-QFN-28-3125x3125TP_L (QFN, 28-Leads, Body 5x5mm, Pitch 0.5mm, Thermal Pad 3.13x3.13mm, IPC High Density)
footprint SLAB-QFN-28-3125x3125TP_M (QFN, 28-Leads, Body 5x5mm, Pitch 0.5mm, Thermal Pad 3.13x3.13mm, IPC Low Density)
pins: 1 P0.1 (io) "Port 0.1.", 2 P0.0 (io) "Port 0.0.", 3 GND (power) "Ground.", 4 D+ (io) "USB D+.", 5 D- (io) "USB D-.", 6 VDD (power) "Power Supply Voltage.", 7 REGIN (power) "5 V Regulator Input. This pin is the input to the on-chip voltage regulator", 8 VBUS (in) "VBUS Sense Input. This pin should be connected to the VBUS signal of a USB network. A 5 V signal on this pin indicates a USB network connection.", 9 ~{RST}/C2CK (io), 10 P3.0/C2D (io), 11 P2.3 (io) "Port 2.3.", 12 P2.2 (io) "Port 2.2.", 13 P2.1 (io) "Port 2.1.", 14 P2.0 (io) "Port 2.0.", 15 P1.7 (io) "Port 1.7.", 16 P1.6 (io) "Port 1.6.", 17 P1.5/VPP (io), 18 P1.4 (io) "Port 1.4.", 19 P1.3 (io) "Port 1.3.", 20 P1.2 (io) "Port 1.2.", 21 P1.1 (io) "Port 1.1.", 22 P1.0 (io) "Port 1.0.", 23 P0.7/VREF (io), 24 P0.6/CNVSTR (io), 25 P0.5 (io) "Port 0.5.", 26 P0.4 (io) "Port 0.4.", 27 P0.3/XTAL2 (io), 28 P0.2/XTAL1 (io), 29 EP (power)

## C8051T326-GM
designator U?
Full Speed USB EPROM MCU Family, 48 MHz, 1.25 kB RAM, 16 kB Flash, -40 to 85 degC, 28-pin QFN; Manufacturer: Silicon Labs; PartNumber: C8051T326-GM; AEC-Q100: FALSE; Debug Interface: C2; Dig I/O Pins: 15; Flash: 16 kB; MCU Core: 8051; MHz: 48; PCA Channels: 5; RAM: 1.25 KB; Temp Sensor: TRUE; Timers (16-bit): 4; Sub-Family: USB MCUs
footprint SLAB-QFN-28-3125x3125TP_N (QFN, 28-Leads, Body 5x5mm, Pitch 0.5mm, Thermal Pad 3.13x3.13mm, IPC Medium Density)
footprint SLAB-QFN-28-3125x3125TP_L (QFN, 28-Leads, Body 5x5mm, Pitch 0.5mm, Thermal Pad 3.13x3.13mm, IPC High Density)
footprint SLAB-QFN-28-3125x3125TP_M (QFN, 28-Leads, Body 5x5mm, Pitch 0.5mm, Thermal Pad 3.13x3.13mm, IPC Low Density)
part A pins: 1 P0.0 (io) "Port 0.0.", 2 GND (power) "Ground.", 3 D+ (io) "USB D+.", 4 D- (io) "USB D-", 5 VIO (power) "V I/O Supply Voltage Input. The voltage at this pin must  be less than or equal to the Core Supply Voltage (VDD).", 6 VDD (power) "Power Supply Voltage.", 7 REGIN (power) "5 V Regulator Input. This pin is the input to the on-chip  voltage regulator.", 8 VBUS (in) "VBUS Sense Input. This pin should be connected to the VBUS signal of a USB network. A 5 V signal on this pin indicates a USB network connection.", 9 ~{RST}/C2CK (io), 10 P3.0/C2D (io), 11 P1.5 (io) "Port 1.5.", 12 P1.4 (io) "Port 1.4.", 16 P1.3 (io) "Port 1.3.", 17 P1.2 (io) "Port 1.2.", 18 P1.1/VPP (io), 19 P1.0 (io) "Port 1.0.", 22 P0.7 (io) "Port 0.7", 23 P0.6 (io) "Port 0.6.", 24 P0.5 (io) "Port 0.5.", 25 P0.4 (io) "Port 0.4.", 26 P0.3/XTAL2 (io), 27 P0.2/XTAL1 (io), 28 P0.1 (io) "Port 0.1.", 29 GND (power)
part B pins: 13 NC, 14 NC, 15 NC, 20 NC, 21 NC

## C8051T327-GM
designator U?
Full Speed USB EPROM MCU Family, 48 MHz, 1.25 kB RAM, 16 kB Flash, -40 to 85 degC, 28-pin QFN; Manufacturer: Silicon Labs; PartNumber: C8051T327-GM; AEC-Q100: FALSE; Debug Interface: C2; Dig I/O Pins: 15; Flash: 16 kB; MCU Core: 8051; MHz: 48; PCA Channels: 5; RAM: 1.25 KB; Temp Sensor: TRUE; Timers (16-bit): 4; Sub-Family: USB MCUs
footprint SLAB-QFN-28-3125x3125TP_N (QFN, 28-Leads, Body 5x5mm, Pitch 0.5mm, Thermal Pad 3.13x3.13mm, IPC Medium Density)
footprint SLAB-QFN-28-3125x3125TP_L (QFN, 28-Leads, Body 5x5mm, Pitch 0.5mm, Thermal Pad 3.13x3.13mm, IPC High Density)
footprint SLAB-QFN-28-3125x3125TP_M (QFN, 28-Leads, Body 5x5mm, Pitch 0.5mm, Thermal Pad 3.13x3.13mm, IPC Low Density)
part A pins: 1 P0.1 (io) "Port 0.1.", 2 P0.0 (io) "Port 0.0.", 3 GND (power) "Ground.", 4 D+ (io) "USB D+.", 5 D- (io) "USB D-", 6 VDD (power) "Power Supply Voltage.", 7 REGIN (power) "5 V Regulator Input. This pin is the input to the on-chip  voltage regulator.", 8 VBUS (in) "VBUS Sense Input. This pin should be connected to the VBUS signal of a USB network. A 5 V signal on this pin indicates a USB network connection.", 9 ~{RST}/C2CK (io), 10 P2.0/C2D (io), 11 P1.5 (io) "Port 1.5.", 12 P1.4 (io) "Port 1.4.", 16 P1.3 (io) "Port 1.3.", 17 P1.2 (io) "Port 1.2.", 18 P1.1/VPP (io), 19 P1.0 (io) "Port 1.0.", 23 P0.7 (io) "Port 0.7", 24 P0.6 (io) "Port 0.6.", 25 P0.5 (io) "Port 0.5.", 26 P0.4 (io) "Port 0.4.", 27 P0.3/XTAL2 (io), 28 P0.2/XTAL1 (io), 29 GND (power)
part B pins: 13 NC, 14 NC, 15 NC, 20 NC, 21 NC, 22 NC

## C8051T620-GM
designator U?
Full Speed USB EPROM MCU Family, 48 MHz, 1.25 kB RAM, 16 kB Flash, -40 to 85 degC, 32-pin QFN; Manufacturer: Silicon Labs; PartNumber: C8051T620-GM; AEC-Q100: FALSE; Comparators: 2; Debug Interface: C2; Dig I/O Pins: 24; Flash: 16 kB; MCU Core: 8051; MHz: 48; PCA Channels: 5; RAM: 1.25 KB; Temp Sensor: TRUE; Timers (16-bit): 4; Sub-Family: USB MCUs
footprint SLAB-QFN-32-3300x3300TP_N (QFN, 32-Leads, Body 5x5mm, Pitch 0.5mm, Thermal Pad 3.3x3.3mm, IPC Medium Density)
footprint SLAB-QFN-32-3300x3300TP_L (QFN, 32-Leads, Body 5x5mm, Pitch 0.5mm, Thermal Pad 3.3x3.3mm, IPC High Density)
footprint SLAB-QFN-32-3300x3300TP_M (QFN, 32-Leads, Body 5x5mm, Pitch 0.5mm, Thermal Pad 3.3x3.3mm, IPC Low Density)
pins: 1 P0.1 (io) "Port 0.1.", 2 P0.0 (io) "Port 0.0.", 3 GND (power) "Ground.", 4 D+ (io) "USB D+.", 5 D- (io) "USB D-.", 6 VIO (power) "V I/O Supply Voltage Input. The voltage at this pin must be less than or equal to the Core Supply Voltage (VDD).", 7 VDD (power) "Power Supply Voltage.", 8 REGIN (power) "5 V Regulator Input. This pin is the input to the on-chip voltage regulator.", 9 VBUS (in) "VBUS Sense Input. This pin should be connected to the VBUS signal of a USB network. A 5 V signal on this pin indicates a USB network connection.", 10 ~{RST}/C2CK (io), 11 P3.0/C2D (io), 12 P2.6 (io) "Port 2.6.", 13 P2.5 (io) "Port 2.5.", 14 P2.4 (io) "Port 2.4.", 15 P2.3 (io) "Port 2.3.", 16 P2.2 (io) "Port 2.2.", 17 P2.1 (io) "Port 2.1.", 18 P2.0 (io) "Port 2.0.", 19 P1.7 (io) "Port 1.7.", 20 P1.6 (io) "Port 1.6.", 21 P1.5/VPP (io), 22 P1.4 (io) "Port 1.4.", 23 P1.3 (io) "Port 1.3.", 24 P1.2 (io) "Port 1.2.", 25 P1.1 (io) "Port 1.1.", 26 P1.0 (io) "Port 1.0.", 27 P0.7/VREF (io), 28 P0.6/CNVSTR (io), 29 P0.5 (io) "Port 0.5.", 30 P0.4 (io) "Port 0.4.", 31 P0.3/XTAL2 (io), 32 P0.2/XTAL1 (io), 33 GND (power) "Ground."

## C8051T621-GM
designator U?
Full Speed USB EPROM MCU Family, 48 MHz, 1.25 kB RAM, 16 kB Flash, -40 to 85 degC, 32-pin QFN; Manufacturer: Silicon Labs; PartNumber: C8051T621-GM; AEC-Q100: FALSE; Comparators: 2; Debug Interface: C2; Dig I/O Pins: 24; Flash: 16 kB; MCU Core: 8051; MHz: 48; PCA Channels: 5; RAM: 1.25 KB; Temp Sensor: TRUE; Timers (16-bit): 4; Sub-Family: USB MCUs
footprint SLAB-QFN-32-3300x3300TP_N (QFN, 32-Leads, Body 5x5mm, Pitch 0.5mm, Thermal Pad 3.3x3.3mm, IPC Medium Density)
footprint SLAB-QFN-32-3300x3300TP_L (QFN, 32-Leads, Body 5x5mm, Pitch 0.5mm, Thermal Pad 3.3x3.3mm, IPC High Density)
footprint SLAB-QFN-32-3300x3300TP_M (QFN, 32-Leads, Body 5x5mm, Pitch 0.5mm, Thermal Pad 3.3x3.3mm, IPC Low Density)
pins: 1 P0.1 (io) "Port 0.1.", 2 P0.0 (io) "Port 0.0.", 3 GND (power) "Ground.", 4 D+ (io) "USB D+.", 5 D- (io) "USB D-.", 6 VIO (power) "V I/O Supply Voltage Input. The voltage at this pin must be less than or equal to the Core Supply Voltage (VDD).", 7 VDD (power) "Power Supply Voltage.", 8 REGIN (power) "5 V Regulator Input. This pin is the input to the on-chip voltage regulator.", 9 VBUS (in) "VBUS Sense Input. This pin should be connected to the VBUS signal of a USB network. A 5 V signal on this pin indicates a USB network connection.", 10 ~{RST}/C2CK (io), 11 P3.0/C2D (io), 12 P2.6 (io) "Port 2.6.", 13 P2.5 (io) "Port 2.5.", 14 P2.4 (io) "Port 2.4.", 15 P2.3 (io) "Port 2.3.", 16 P2.2 (io) "Port 2.2.", 17 P2.1 (io) "Port 2.1.", 18 P2.0 (io) "Port 2.0.", 19 P1.7 (io) "Port 1.7.", 20 P1.6 (io) "Port 1.6.", 21 P1.5/VPP (io), 22 P1.4 (io) "Port 1.4.", 23 P1.3 (io) "Port 1.3.", 24 P1.2 (io) "Port 1.2.", 25 P1.1 (io) "Port 1.1.", 26 P1.0 (io) "Port 1.0.", 27 P0.7/VREF (io), 28 P0.6/CNVSTR (io), 29 P0.5 (io) "Port 0.5.", 30 P0.4 (io) "Port 0.4.", 31 P0.3/XTAL2 (io), 32 P0.2/XTAL1 (io), 33 GND (power) "Ground."

## C8051T622-GM
designator U?
Full Speed USB EPROM MCU Family, 48 MHz, 1.25 kB RAM, 16 kB Flash, -40 to 85 degC, 24-pin QFN; Manufacturer: Silicon Labs; PartNumber: C8051T622-GM; AEC-Q100: FALSE; Debug Interface: C2; Dig I/O Pins: 16; Flash: 16 kB; Internal Osc. Accuracy: +/-1.5%; MCU Core: 8051; MHz: 48; PCA Channels: 5; RAM: 1.25 KB; Temp Sensor: TRUE; Timers (16-bit): 4; Sub-Family: USB MCUs
footprint SLAB-QFN-24-2675x2675TP_N (QFN, 24-Leads, Body 4x4mm, Pitch 0.5mm, Thermal Pad 2.68x2.68mm, IPC Medium Density)
footprint SLAB-QFN-24-2675x2675TP_L (QFN, 24-Leads, Body 4x4mm, Pitch 0.5mm, Thermal Pad 2.68x2.68mm, IPC High Density)
footprint SLAB-QFN-24-2675x2675TP_M (QFN, 24-Leads, Body 4x4mm, Pitch 0.5mm, Thermal Pad 2.68x2.68mm, IPC Low Density)
pins: 1 P0.0 (io) "Port 0.0.", 2 GND (power) "Ground.", 3 D+ (io) "USB D+.", 4 D- (io) "USB D-.", 5 VIO (power) "V I/O Supply Voltage Input. The voltage at this pin must be less than or equal to the Core Supply Voltage (VDD).", 6 VDD (power) "Power Supply Voltage.", 7 REGIN (power) "5 V Regulator Input. This pin is the input to the on-chip voltage regulator.", 8 VBUS (in) "VBUS Sense Input. This pin should be connected to the VBUS signal of a USB network. A 5 V signal on this pin indicates a USB network connection.", 9 ~{RST}/C2CK (io), 10 P2.0/C2D (io), 11 P1.6 (io) "Port 1.6.", 12 P1.5 (io) "Port 1.5.", 13 P1.4 (io) "Port 1.4.", 14 P1.3 (io) "Port 1.3.", 15 P1.2 (io) "Port 1.2.", 16 P1.1/VPP (io), 17 P1.0 (io) "Port 1.0.", 18 P0.7 (io) "Port 0.7", 19 P0.6 (io) "Port 0.6.", 20 P0.5 (io) "Port 0.5.", 21 P0.4 (io) "Port 0.4.", 22 P0.3/XTAL2 (io), 23 P0.2/XTAL1 (io), 24 P0.1 (io) "Port 0.1.", 25 GND (power) "Ground."

## C8051T623-GM
designator U?
Full Speed USB EPROM MCU Family, 48 MHz, 1.25 kB RAM, 8 kB Flash, -40 to 85 degC, 24-pin QFN; Manufacturer: Silicon Labs; PartNumber: C8051T623-GM; AEC-Q100: FALSE; Debug Interface: C2; Dig I/O Pins: 16; Flash: 8 kB; Internal Osc. Accuracy: +/-1.5%; MCU Core: 8051; MHz: 48; PCA Channels: 5; RAM: 1.25 KB; Temp Sensor: TRUE; Timers (16-bit): 4; Sub-Family: USB MCUs
footprint SLAB-QFN-24-2675x2675TP_N (QFN, 24-Leads, Body 4x4mm, Pitch 0.5mm, Thermal Pad 2.68x2.68mm, IPC Medium Density)
footprint SLAB-QFN-24-2675x2675TP_L (QFN, 24-Leads, Body 4x4mm, Pitch 0.5mm, Thermal Pad 2.68x2.68mm, IPC High Density)
footprint SLAB-QFN-24-2675x2675TP_M (QFN, 24-Leads, Body 4x4mm, Pitch 0.5mm, Thermal Pad 2.68x2.68mm, IPC Low Density)
pins: 1 P0.0 (io) "Port 0.0.", 2 GND (power) "Ground.", 3 D+ (io) "USB D+.", 4 D- (io) "USB D-.", 5 VIO (power) "V I/O Supply Voltage Input. The voltage at this pin must be less than or equal to the Core Supply Voltage (VDD).", 6 VDD (power) "Power Supply Voltage.", 7 REGIN (power) "5 V Regulator Input. This pin is the input to the on-chip voltage regulator.", 8 VBUS (in) "VBUS Sense Input. This pin should be connected to the VBUS signal of a USB network. A 5 V signal on this pin indicates a USB network connection.", 9 ~{RST}/C2CK (io), 10 P2.0/C2D (io), 11 P1.6 (io) "Port 1.6.", 12 P1.5 (io) "Port 1.5.", 13 P1.4 (io) "Port 1.4.", 14 P1.3 (io) "Port 1.3.", 15 P1.2 (io) "Port 1.2.", 16 P1.1/VPP (io), 17 P1.0 (io) "Port 1.0.", 18 P0.7 (io) "Port 0.7", 19 P0.6 (io) "Port 0.6.", 20 P0.5 (io) "Port 0.5.", 21 P0.4 (io) "Port 0.4.", 22 P0.3/XTAL2 (io), 23 P0.2/XTAL1 (io), 24 P0.1 (io) "Port 0.1.", 25 GND (power) "Ground."

## C8051T626-B-GM
designator U?
Full Speed USB EPROM MCU Family, 48 MHz, 3.25 kB RAM, 64 kB Flash, -40 to 85 degC, 32-pin QFN; Manufacturer: Silicon Labs; PartNumber: C8051T626-B-GM; ADC 1: 10-bit, 21-ch., 500 ksps; AEC-Q100: FALSE; Comparators: 2; Debug Interface: C2; Dig I/O Pins: 24; Flash: 64 kB; Internal Osc. Accuracy: +/-0.25%; MCU Core: 8051; MHz: 48; PCA Channels: 5; RAM: 3.25 KB; Temp Sensor: TRUE; Timers (16-bit): 4; Sub-Family: USB MCUs
footprint SLAB-QFN-32-3300x3300TP_N (QFN, 32-Leads, Body 5x5mm, Pitch 0.5mm, Thermal Pad 3.3x3.3mm, IPC Medium Density)
footprint SLAB-QFN-32-3300x3300TP_L (QFN, 32-Leads, Body 5x5mm, Pitch 0.5mm, Thermal Pad 3.3x3.3mm, IPC High Density)
footprint SLAB-QFN-32-3300x3300TP_M (QFN, 32-Leads, Body 5x5mm, Pitch 0.5mm, Thermal Pad 3.3x3.3mm, IPC Low Density)
pins: 1 P0.1 (io) "Port 0.1.", 2 P0.0 (io) "Port 0.0.", 3 GND (power) "Ground.", 4 D+ (io) "USB D+.", 5 D- (io) "USB D-.", 6 VIO (power) "V I/O Supply Voltage Input. The voltage at this pin must be less than or equal to the Core Supply Voltage (VDD).", 7 VDD (power) "Power Supply Voltage.", 8 REGIN (power) "5 V Regulator Input. This pin is the input to the on-chip voltage regulator.", 9 VBUS (in) "VBUS Sense Input. This pin should be connected to the VBUS signal of a USB network. A 5 V signal on this pin indicates a USB network connection.", 10 ~{RST}/C2CK (io), 11 P3.0/C2D (io), 12 P2.6 (io) "Port 2.6.", 13 P2.5 (io) "Port 2.5.", 14 P2.4 (io) "Port 2.4.", 15 P2.3 (io) "Port 2.3.", 16 P2.2 (io) "Port 2.2.", 17 P2.1 (io) "Port 2.1.", 18 P2.0 (io) "Port 2.0.", 19 P1.7 (io) "Port 1.7.", 20 P1.6 (io) "Port 1.6.", 21 P1.5/VPP (io), 22 P1.4 (io) "Port 1.4.", 23 P1.3 (io) "Port 1.3.", 24 P1.2 (io) "Port 1.2.", 25 P1.1 (io) "Port 1.1.", 26 P1.0 (io) "Port 1.0.", 27 P0.7/VREF (io), 28 P0.6/CNVSTR (io), 29 P0.5 (io) "Port 0.5.", 30 P0.4 (io) "Port 0.4.", 31 P0.3/XTAL2 (io), 32 P0.2/XTAL1 (io), 33 GND (power) "Ground."

## C8051T627-B-GM
designator U?
Full Speed USB EPROM MCU Family, 48 MHz, 3.25 kB RAM, 32 kB Flash, -40 to 85 degC, 32-pin QFN; Manufacturer: Silicon Labs; PartNumber: C8051T627-B-GM; ADC 1: 10-bit, 21-ch., 500 ksps; AEC-Q100: FALSE; Comparators: 2; Debug Interface: C2; Dig I/O Pins: 24; Flash: 32 kB; Internal Osc. Accuracy: +/-0.25%; MCU Core: 8051; MHz: 48; PCA Channels: 5; RAM: 3.25 KB; Temp Sensor: TRUE; Timers (16-bit): 4; Sub-Family: USB MCUs
footprint SLAB-QFN-32-3300x3300TP_N (QFN, 32-Leads, Body 5x5mm, Pitch 0.5mm, Thermal Pad 3.3x3.3mm, IPC Medium Density)
footprint SLAB-QFN-32-3300x3300TP_L (QFN, 32-Leads, Body 5x5mm, Pitch 0.5mm, Thermal Pad 3.3x3.3mm, IPC High Density)
footprint SLAB-QFN-32-3300x3300TP_M (QFN, 32-Leads, Body 5x5mm, Pitch 0.5mm, Thermal Pad 3.3x3.3mm, IPC Low Density)
pins: 1 P0.1 (io) "Port 0.1.", 2 P0.0 (io) "Port 0.0.", 3 GND (power) "Ground.", 4 D+ (io) "USB D+.", 5 D- (io) "USB D-.", 6 VIO (power) "V I/O Supply Voltage Input. The voltage at this pin must be less than or equal to the Core Supply Voltage (VDD).", 7 VDD (power) "Power Supply Voltage.", 8 REGIN (power) "5 V Regulator Input. This pin is the input to the on-chip voltage regulator.", 9 VBUS (in) "VBUS Sense Input. This pin should be connected to the VBUS signal of a USB network. A 5 V signal on this pin indicates a USB network connection.", 10 ~{RST}/C2CK (io), 11 P3.0/C2D (io), 12 P2.6 (io) "Port 2.6.", 13 P2.5 (io) "Port 2.5.", 14 P2.4 (io) "Port 2.4.", 15 P2.3 (io) "Port 2.3.", 16 P2.2 (io) "Port 2.2.", 17 P2.1 (io) "Port 2.1.", 18 P2.0 (io) "Port 2.0.", 19 P1.7 (io) "Port 1.7.", 20 P1.6 (io) "Port 1.6.", 21 P1.5/VPP (io), 22 P1.4 (io) "Port 1.4.", 23 P1.3 (io) "Port 1.3.", 24 P1.2 (io) "Port 1.2.", 25 P1.1 (io) "Port 1.1.", 26 P1.0 (io) "Port 1.0.", 27 P0.7/VREF (io), 28 P0.6/CNVSTR (io), 29 P0.5 (io) "Port 0.5.", 30 P0.4 (io) "Port 0.4.", 31 P0.3/XTAL2 (io), 32 P0.2/XTAL1 (io), 33 GND (power) "Ground."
